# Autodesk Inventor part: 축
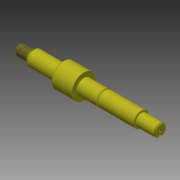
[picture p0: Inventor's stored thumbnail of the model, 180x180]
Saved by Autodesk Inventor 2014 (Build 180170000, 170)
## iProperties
Created: 2016-08
Part Number: 축
Material: 강철, 탄소
Document SubType Name: Modeling
Designer: mduedu
Density: 7.87 g/cm^3
Appearance: 밝은 황색
Author: mduedu
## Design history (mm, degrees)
sketch "스케치1"
  geometry: L1 (-70, 0)-(70, 0); L2 (-70, 0)-(-70, 5); L3 (-70, 5)-(-56, 5); L4 (-56, 5)-(-56, 7.5); L5 (-56, 7.5)-(51, 7.5); L6 (51, 7.5)-(51, 6); L7 (51, 6)-(70, 6); L8 (70, 6)-(70, 0); 2 further points
  constraints: 16 end point, 5 parallel, 2 perpendicular, 1 coincident, 1 horizontal, 1 midpoint
  dimensions: "d0" = 140 distance of L1.start L1.end; "d2" = 14 distance of L2.end L3.end; "d3" = 19 distance of L6.end L7.end; "d4" = 10 diameter of L3 L1; "d5" = 15 diameter of L5 L1; "d6" = 12 diameter of L7 L1
revolve "회전1" sketch "스케치1" stored, may be unused: angle "d7" = 90 deg
sketch "스케치2"
  geometry: L1 (-56, -5)-(-56, 5) reference; L2 (70, -6)-(70, 6) reference; L3 (-56, 0)-(70, 0); L4 (-58, 4.5)-(-58, 5); L5 (-58, 5)-(-56, 5); L6 (-56, 5)-(-56, 4.5); L7 (-58, 4.5)-(-56, 4.5); 1 further point
  constraints: 10 end point, 2 midpoint, 1 parallel, 1 perpendicular, 1 point on line
  dimensions: "d8" = 2 distance of L4.end L5.end; "d10" = 10 diameter of L5 L3; "d11" = 9 diameter of L7 L3
revolve "회전2" sketch "스케치2" stored, may be unused: angle "d12" = 90 deg
node "작업 평면1"
sketch "스케치3"
  geometry: C1 r 12 at (0, 0); 1 further point
  constraints: 1 centre point, 1 coincident
  dimensions: "d15" = 24 diameter of C1
extrude "돌출1" join sketch "스케치3" distance "d16" = 20; taper "d17" = 0 deg
sketch "스케치5"
  geometry: L1 (-70, -5)-(-70, 5) reference; L2 (70, -6)-(70, 6) reference; L3 (-70, 0)-(70, 0); L4 (-6, 7.5)-(51, 7.5) reference; L5 (15.15, 7.5)-(14, 7.5); L6 (14, 7.5)-(14, 7.15); L7 (14, 7.15)-(15.15, 7.15); L8 (15.15, 7.15)-(15.15, 7.5); 1 further point
  constraints: 10 end point, 2 midpoint, 2 parallel, 1 horizontal, 1 perpendicular, 1 point on line
  dimensions: "d19" = 56 distance between parallel lines of L6 L2; "d20" = 1.15 distance between parallel lines of L8 L6; "d21" = 14.3 diameter of L7 L3
revolve "회전3" sketch "스케치5" stored, may be unused: angle "d22" = 90 deg
node "작업 평면3"
sketch "스케치6"
  geometry: L1 (9.5, 7.5)-(9.5, -7.5) reference; L2 (7.5, 2)-(-9.5, 2); L3 (-9.5, 2)-(-9.5, -2); L4 (-9.5, -2)-(7.5, -2); L5 (-9.5, 6)-(-9.5, -6) reference; A1 r 2 centre (7.5, 0) between (7.5, -2) and (7.5, 2); 2 further points
  constraints: 6 end point, 3 tangent, 2 midpoint, 2 point on circle, 1 centre point, 1 horizontal, 1 horizontal alignment, 1 parallel, 1 perpendicular
  dimensions: "d23" = 4 distance between parallel lines of L4 L2
extrude "돌출2" cut sketch "스케치6" distance "d25" = 2.5; taper "d26" = 0 deg
feature "스레드1" dims "d27" = 10, "d28" = 0
chamfer "모따기5" distance "d41" = 0.5; stored, may be unused: second distance "d42" = 2, angle "d43" = 45 deg
chamfer "모따기6" distance "d44" = 0.5; stored, may be unused: second distance "d45" = 2, angle "d46" = 45 deg
chamfer "모따기7" distance "d47" = 1; stored, may be unused: second distance "d48" = 2, angle "d49" = 45 deg
chamfer "모따기8" distance "d50" = 1; stored, may be unused: second distance "d51" = 2, angle "d52" = 45 deg
sketch "스케치8"
  geometry: 1 further point
hole "구멍1" sketch "스케치8" at (2, 3.5) diameter "d53" = 3.242; stored, may be unused: countersink angle "d57" = 90 deg, drill point angle "d59" = 120 deg; dims "d54" = 10, "d55" = 4, "d56" = 2, "d58" = 12
node "솔리드1"
other parameters: "d13" = -44
